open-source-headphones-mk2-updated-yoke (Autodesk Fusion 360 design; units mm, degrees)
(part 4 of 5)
sketch "50mm PM Label" plane through (0, 0, 0) normal (0, 0, -1) x axis (1, 0, 0)
  line L1 (1, -18.9737) -> (1, -23.9792)
  line L2 (14.6475, -19.0119) -> (11.43, -15.1775)
  line L3 (9.9868, 4.6112) -> (6.5, 2.5981)
  line L4 (1, -6.9282) -> (1, -10.9545)
  line L5 (1, 16.9706) -> (1, 12.9615)
  line L6 (10.725, 7.3468) -> (14.1969, 9.3513)
  line L7 (-8.9868, 6.3433) -> (-5.5, 4.3301)
  line L8 (5.5, 4.3301) -> (8.9868, 6.3433)
  line L9 (-1, -16.9706) -> (-1, -12.9615)
  line L10 (-10.725, -7.3468) -> (-14.1969, -9.3513)
  line L11 (-11.725, 5.6147) -> (-15.1969, 7.6193)
  line L12 (-15.1969, -7.6193) -> (-11.725, -5.6147)
  line L13 (11.725, -5.6147) -> (15.1969, -7.6193)
  line L14 (15.1969, 7.6193) -> (11.725, 5.6147)
  line L15 (1, -12.9615) -> (1, -16.9706)
  line L16 (14.1969, -9.3513) -> (10.725, -7.3468)
  line L17 (-1, 12.9615) -> (-1, 16.9706)
  line L18 (-14.1969, 9.3513) -> (-10.725, 7.3468)
  line L19 (-1, -10.9545) -> (-1, -6.9282)
  line L20 (-6.5, 2.5981) -> (-9.9868, 4.6112)
  line L21 (-11.43, -15.1775) -> (-14.6475, -19.0119)
  line L22 (-1, -23.9792) -> (-1, -18.9737)
  line L23 (-18.5118, -4.2796) -> (-23.4412, -5.1487)
  line L24 (-16.1795, -17.7263) -> (-12.9621, -13.8919)
  line L25 (-16.9317, 8.6208) -> (-21.2666, 11.1236)
  line L26 (-23.7885, -3.1791) -> (-18.8591, -2.3099)
  line L27 (-7.4291, 17.4874) -> (-9.141, 22.191)
  line L28 (-20.2666, 12.8556) -> (-15.9317, 10.3529)
  line L29 (5.5497, 18.1714) -> (7.2617, 22.8751)
  line L30 (-7.2617, 22.8751) -> (-5.5497, 18.1714)
  line L31 (15.9317, 10.3529) -> (20.2666, 12.8556)
  line L32 (9.141, 22.191) -> (7.4291, 17.4874)
  line L33 (18.8591, -2.3099) -> (23.7885, -3.1791)
  line L34 (21.2666, 11.1236) -> (16.9317, 8.6208)
  line L35 (12.9621, -13.8919) -> (16.1795, -17.7263)
  line L36 (23.4412, -5.1487) -> (18.5118, -4.2796)
  line L37 (27.3973, 19.1838) -> (24.0432, 16.8352)
  line L38 (24.0432, -16.8352) -> (27.3973, -19.1838)
  line L39 (-17.7523, 28.4096) -> (-15.6326, 25.0174)
  line L40 (15.6326, 25.0174) -> (17.7523, 28.4096)
  line L41 (-27.3973, -19.1838) -> (-24.0432, -16.8352)
  line L42 (-24.0432, 16.8352) -> (-27.3973, 19.1838)
  line L43 (17.7523, -28.4096) -> (15.6326, -25.0174)
  line L44 (-15.6326, -25.0174) -> (-17.7523, -28.4096)
  curve K1 (0, 52) -> (0, 52)
  curve K2
  curve K3
  curve K4
  curve K5
  arc A1 centre (0, 0) radius 19 clockwise from (11.43, -15.1775) to (1, -18.9737)
  arc A2 centre (0, 0) radius 24 clockwise from (14.6475, -19.0119) to (1, -23.9792)
  arc A3 centre (0, 0) radius 11 clockwise from (9.9868, 4.6112) to (1, -10.9545)
  arc A4 centre (0, 0) radius 7 clockwise from (6.5, 2.5981) to (1, -6.9282)
  arc A5 centre (0, 0) radius 17 clockwise from (1, 16.9706) to (14.1969, 9.3513)
  arc A6 centre (0, 0) radius 13 clockwise from (1, 12.9615) to (10.725, 7.3468)
  circle C1 centre (0, 0) radius 5
  arc A7 centre (0, 0) radius 11 clockwise from (-8.9868, 6.3433) to (8.9868, 6.3433)
  arc A8 centre (0, 0) radius 7 clockwise from (-5.5, 4.3301) to (5.5, 4.3301)
  arc A9 centre (0, 0) radius 17 clockwise from (-1, -16.9706) to (-14.1969, -9.3513)
  arc A10 centre (0, 0) radius 13 clockwise from (-1, -12.9615) to (-10.725, -7.3468)
  arc A11 centre (0, 0) radius 17 clockwise from (-15.1969, -7.6193) to (-15.1969, 7.6193)
  arc A12 centre (0, 0) radius 13 clockwise from (-11.725, -5.6147) to (-11.725, 5.6147)
  arc A13 centre (0, 0) radius 17 clockwise from (15.1969, 7.6193) to (15.1969, -7.6193)
  arc A14 centre (0, 0) radius 13 clockwise from (11.725, 5.6147) to (11.725, -5.6147)
  arc A15 centre (0, 0) radius 17 clockwise from (14.1969, -9.3513) to (1, -16.9706)
  arc A16 centre (0, 0) radius 13 clockwise from (10.725, -7.3468) to (1, -12.9615)
  arc A17 centre (0, 0) radius 17 clockwise from (-14.1969, 9.3513) to (-1, 16.9706)
  arc A18 centre (0, 0) radius 13 clockwise from (-10.725, 7.3468) to (-1, 12.9615)
  arc A19 centre (0, 0) radius 11 clockwise from (-1, -10.9545) to (-9.9868, 4.6112)
  arc A20 centre (0, 0) radius 7 clockwise from (-1, -6.9282) to (-6.5, 2.5981)
  arc A21 centre (0, 0) radius 19 clockwise from (-1, -18.9737) to (-11.43, -15.1775)
  arc A22 centre (0, 0) radius 24 clockwise from (-1, -23.9792) to (-14.6475, -19.0119)
  arc A23 centre (0, 0) radius 19 clockwise from (-12.9621, -13.8919) to (-18.5118, -4.2796)
  arc A24 centre (0, 0) radius 24 clockwise from (-16.1795, -17.7263) to (-23.4412, -5.1487)
  arc A25 centre (0, 0) radius 19 clockwise from (-18.8591, -2.3099) to (-16.9317, 8.6208)
  arc A26 centre (0, 0) radius 24 clockwise from (-23.7885, -3.1791) to (-21.2666, 11.1236)
  arc A27 centre (0, 0) radius 19 clockwise from (-15.9317, 10.3529) to (-7.4291, 17.4874)
  arc A28 centre (0, 0) radius 24 clockwise from (-20.2666, 12.8556) to (-9.141, 22.191)
  arc A29 centre (0, 0) radius 19 clockwise from (-5.5497, 18.1714) to (5.5497, 18.1714)
  arc A30 centre (0, 0) radius 24 clockwise from (-7.2617, 22.8751) to (7.2617, 22.8751)
  arc A31 centre (0, 0) radius 19 clockwise from (7.4291, 17.4874) to (15.9317, 10.3529)
  arc A32 centre (0, 0) radius 24 clockwise from (9.141, 22.191) to (20.2666, 12.8556)
  arc A33 centre (0, 0) radius 19 clockwise from (16.9317, 8.6208) to (18.8591, -2.3099)
  arc A34 centre (0, 0) radius 24 clockwise from (21.2666, 11.1236) to (23.7885, -3.1791)
  arc A35 centre (0, 0) radius 24 clockwise from (23.4412, -5.1487) to (16.1795, -17.7263)
  arc A36 centre (0, 0) radius 19 clockwise from (18.5118, -4.2796) to (12.9621, -13.8919)
  closed curve K6 centre (0, 0)
  closed curve K7 centre (0, 0)
  arc A37 centre (0, 0) radius 33.5 clockwise from (-17.7523, 28.4096) to (17.7523, 28.4096)
  arc A38 centre (0, 0) radius 29.5 clockwise from (-15.6326, 25.0174) to (15.6326, 25.0174)
  closed curve K8 centre (0, 0)
  closed curve K9 centre (0, 0)
  arc A39 centre (0, 0) radius 33.5 clockwise from (17.7523, -28.4096) to (-17.7523, -28.4096)
  arc A40 centre (0, 0) radius 29.5 clockwise from (15.6326, -25.0174) to (-15.6326, -25.0174)
  circle C2 centre (-22.8469, 24.5003) radius 4
  circle C3 centre (22.8469, 24.5003) radius 4
  circle C4 centre (-22.8469, -24.5003) radius 4
  circle C5 centre (22.8469, -24.5003) radius 4
  coincident K1
  dimension "d517" Text1-Height = 10
extrude "Extrude28" cut sketch "50mm PM Label" against normal blind 0.5
sketch "50mm DC Label" plane through (0, 0, 20) normal (0, 0, -1) x axis (1, 0, 0)
  line L1 (8, 23.8964) -> (8, 32.5308)
  line L2 (-8, 32.5308) -> (-8, 23.8964)
  line L3 (27.3973, 19.1838) -> (24.0432, 16.8352)
  line L4 (24.0432, -16.8352) -> (27.3973, -19.1838)
  line L5 (17.7523, -28.4096) -> (15.6326, -25.0174)
  line L6 (-15.6326, -25.0174) -> (-17.7523, -28.4096)
  line L7 (-27.3973, -19.1838) -> (-24.0432, -16.8352)
  line L8 (-24.0432, 16.8352) -> (-27.3973, 19.1838)
  line L9 (6, 55.0308) -> (8, 54.1239)
  line L10 (-6, 55.0308) -> (6, 55.0308)
  line L11 (-8, 54.1239) -> (-6, 55.0308)
  curve K1
  curve K2
  curve K3
  curve K4
  line L12 (45, -1.2179) -> (45, -5.5)
  line L13 (48, -1.2179) -> (45, -1.2179)
  line L14 (48, 3.5) -> (48, -1.2179)
  line L15 (45, 3.5) -> (48, 3.5)
  line L16 (45, 5.5) -> (45, 3.5)
  line L17 (44.7744, 5.5) -> (45, 5.5)
  line L18 (-45, 5.5) -> (-44.7744, 5.5)
  line L19 (-45, 3.5) -> (-45, 5.5)
  line L20 (-48, 3.5) -> (-45, 3.5)
  line L21 (-48, -1.2179) -> (-48, 3.5)
  line L22 (-45, -1.2179) -> (-48, -1.2179)
  line L23 (-45, -5.5) -> (-45, -1.2179)
  line L24 (-44.7744, -5.5) -> (-45, -5.5)
  line L25 (45, -5.5) -> (44.7744, -5.5)
  arc A1 centre (0, 0) radius 25.2 clockwise from (8, 23.8964) to (-8, 23.8964)
  arc A2 centre (0, 0) radius 33.5 clockwise from (-8, 32.5308) to (8, 32.5308)
  closed curve K5 centre (0, 0)
  closed curve K6 centre (0, 0)
  arc A3 centre (0, 0) radius 27.5 clockwise from (26.4189, 7.6348) to (26.4189, -7.6348)
  closed curve K7 centre (0, 0)
  circle C1 centre (22.8469, -24.5003) radius 2.2
  circle C2 centre (22.8469, 24.5003) radius 2.2
  circle C3 centre (-22.8469, -24.5003) radius 2.2
  circle C4 centre (-22.8469, 24.5003) radius 2.2
  arc A4 centre (0, 0) radius 33.5 clockwise from (17.7523, -28.4096) to (-17.7523, -28.4096)
  arc A5 centre (0, 0) radius 29.5 clockwise from (15.6326, -25.0174) to (-15.6326, -25.0174)
  closed curve K8 centre (0, 0)
  closed curve K9 centre (0, 0)
  closed curve K10 centre (0, 0)
  closed curve K11 centre (0, 0)
  arc A6 centre (0, 0) radius 27.5 clockwise from (-26.4189, -7.6348) to (-26.4189, 7.6348)
  closed curve K12 centre (0, 0)
  closed curve K13 centre (0, 0)
  dimension "d520" Text1-Height = 10
extrude "Extrude29" cut sketch "50mm DC Label" against normal blind 0.5
sketch "52mm PM Label" plane through (0, 0, 0) normal (0, 0, -1) x axis (1, 0, 0)
  line L1 (101, -19.975) -> (101, -24.98)
  line L2 (115.2908, -19.7786) -> (112.0736, -15.9445)
  line L3 (109.9868, 4.6112) -> (106.5, 2.5981)
  line L4 (101, -6.9282) -> (101, -10.9545)
  line L5 (101, 17.9722) -> (101, 12.9615)
  line L6 (110.725, 7.3468) -> (115.0644, 9.8521)
  line L7 (91.0132, 6.3433) -> (94.5, 4.3301)
  line L8 (105.5, 4.3301) -> (108.9868, 6.3433)
  line L9 (99, -17.9722) -> (99, -12.9615)
  line L10 (89.275, -7.3468) -> (84.9356, -9.8521)
  line L11 (88.275, 5.6147) -> (83.9356, 8.1201)
  line L12 (83.9356, -8.1201) -> (88.275, -5.6147)
  line L13 (111.725, -5.6147) -> (116.0644, -8.1201)
  line L14 (116.0644, 8.1201) -> (111.725, 5.6147)
  line L15 (101, -12.9615) -> (101, -17.9722)
  line L16 (115.0644, -9.8521) -> (110.725, -7.3468)
  line L17 (99, 12.9615) -> (99, 17.9722)
  line L18 (84.9356, 9.8521) -> (89.275, 7.3468)
  line L19 (99, -10.9545) -> (99, -6.9282)
  line L20 (93.5, 2.5981) -> (90.0132, 4.6112)
  line L21 (87.9264, -15.9445) -> (84.7092, -19.7786)
  line L22 (99, -24.98) -> (99, -19.975)
  line L23 (80.5021, -4.4534) -> (75.5732, -5.3225)
  line L24 (83.1771, -18.493) -> (86.3943, -14.6589)
  line L25 (82.2012, 9.1215) -> (77.8667, 11.624)
  line L26 (75.2259, -3.3529) -> (80.1548, -2.4838)
  line L27 (92.2285, 18.4283) -> (90.5166, 23.1315)
  line L28 (78.8667, 13.356) -> (83.2012, 10.8535)
  line L29 (105.8922, 19.1124) -> (107.604, 23.8155)
  line L30 (92.396, 23.8155) -> (94.1078, 19.1124)
  line L31 (116.7988, 10.8535) -> (121.1333, 13.356)
  line L32 (109.4834, 23.1315) -> (107.7715, 18.4283)
  line L33 (119.8452, -2.4838) -> (124.7741, -3.3529)
  line L34 (122.1333, 11.624) -> (117.7988, 9.1215)
  line L35 (113.6057, -14.6589) -> (116.8229, -18.493)
  line L36 (124.4268, -5.3225) -> (119.4979, -4.4534)
  line L37 (127.3973, 19.1838) -> (124.8888, 17.4274)
  line L38 (124.8888, -17.4274) -> (127.3973, -19.1838)
  curve K1 (124.8888, -17.4274) -> (124.8888, 17.4274)
  line L39 (82.2477, 28.4096) -> (84.3674, 25.0174)
  line L40 (115.6326, 25.0174) -> (117.7523, 28.4096)
  line L41 (72.6027, -19.1838) -> (75.1112, -17.4274)
  line L42 (75.1112, 17.4274) -> (72.6027, 19.1838)
  curve K2 (75.1112, 17.4274) -> (75.1112, -17.4274)
  line L43 (117.7523, -28.4096) -> (115.6326, -25.0174)
  line L44 (84.3674, -25.0174) -> (82.2477, -28.4096)
  curve K3 (100, 52) -> (100, 52)
  curve K4
  curve K5
  curve K6
  curve K7
  arc A1 centre (100, 0) radius 20 clockwise from (112.0736, -15.9445) to (101, -19.975)
  arc A2 centre (100, 0) radius 25 clockwise from (115.2908, -19.7786) to (101, -24.98)
  arc A3 centre (100, 0) radius 11 clockwise from (109.9868, 4.6112) to (101, -10.9545)
  arc A4 centre (100, 0) radius 7 clockwise from (106.5, 2.5981) to (101, -6.9282)
  arc A5 centre (100, 0) radius 18 clockwise from (101, 17.9722) to (115.0644, 9.8521)
  arc A6 centre (100, 0) radius 13 clockwise from (101, 12.9615) to (110.725, 7.3468)
  circle C1 centre (100, 0) radius 5
  arc A7 centre (100, 0) radius 11 clockwise from (91.0132, 6.3433) to (108.9868, 6.3433)
  arc A8 centre (100, 0) radius 7 clockwise from (94.5, 4.3301) to (105.5, 4.3301)
  arc A9 centre (100, 0) radius 18 clockwise from (99, -17.9722) to (84.9356, -9.8521)
  arc A10 centre (100, 0) radius 13 clockwise from (99, -12.9615) to (89.275, -7.3468)
  arc A11 centre (100, 0) radius 18 clockwise from (83.9356, -8.1201) to (83.9356, 8.1201)
  arc A12 centre (100, 0) radius 13 clockwise from (88.275, -5.6147) to (88.275, 5.6147)
  arc A13 centre (100, 0) radius 18 clockwise from (116.0644, 8.1201) to (116.0644, -8.1201)
  arc A14 centre (100, 0) radius 13 clockwise from (111.725, 5.6147) to (111.725, -5.6147)
  arc A15 centre (100, 0) radius 18 clockwise from (115.0644, -9.8521) to (101, -17.9722)
  arc A16 centre (100, 0) radius 13 clockwise from (110.725, -7.3468) to (101, -12.9615)
  arc A17 centre (100, 0) radius 18 clockwise from (84.9356, 9.8521) to (99, 17.9722)
  arc A18 centre (100, 0) radius 13 clockwise from (89.275, 7.3468) to (99, 12.9615)
  arc A19 centre (100, 0) radius 11 clockwise from (99, -10.9545) to (90.0132, 4.6112)
  arc A20 centre (100, 0) radius 7 clockwise from (99, -6.9282) to (93.5, 2.5981)
  arc A21 centre (100, 0) radius 20 clockwise from (99, -19.975) to (87.9264, -15.9445)
  arc A22 centre (100, 0) radius 25 clockwise from (99, -24.98) to (84.7092, -19.7786)
  arc A23 centre (100, 0) radius 20 clockwise from (86.3943, -14.6589) to (80.5021, -4.4534)
  arc A24 centre (100, 0) radius 25 clockwise from (83.1771, -18.493) to (75.5732, -5.3225)
  arc A25 centre (100, 0) radius 20 clockwise from (80.1548, -2.4838) to (82.2012, 9.1215)
  arc A26 centre (100, 0) radius 25 clockwise from (75.2259, -3.3529) to (77.8667, 11.624)
  arc A27 centre (100, 0) radius 20 clockwise from (83.2012, 10.8535) to (92.2285, 18.4283)
  arc A28 centre (100, 0) radius 25 clockwise from (78.8667, 13.356) to (90.5166, 23.1315)
  arc A29 centre (100, 0) radius 20 clockwise from (94.1078, 19.1124) to (105.8922, 19.1124)
  arc A30 centre (100, 0) radius 25 clockwise from (92.396, 23.8155) to (107.604, 23.8155)
  arc A31 centre (100, 0) radius 20 clockwise from (107.7715, 18.4283) to (116.7988, 10.8535)
  arc A32 centre (100, 0) radius 25 clockwise from (109.4834, 23.1315) to (121.1333, 13.356)
  arc A33 centre (100, 0) radius 20 clockwise from (117.7988, 9.1215) to (119.8452, -2.4838)
  arc A34 centre (100, 0) radius 25 clockwise from (122.1333, 11.624) to (124.7741, -3.3529)
  arc A35 centre (100, 0) radius 25 clockwise from (124.4268, -5.3225) to (116.8229, -18.493)
  arc A36 centre (100, 0) radius 20 clockwise from (119.4979, -4.4534) to (113.6057, -14.6589)
  closed curve K8 centre (100, 0)
  arc A37 centre (100, 0) radius 33.5 clockwise from (82.2477, 28.4096) to (117.7523, 28.4096)
  arc A38 centre (100, 0) radius 29.5 clockwise from (84.3674, 25.0174) to (115.6326, 25.0174)
  closed curve K9 centre (100, 0)
  arc A39 centre (100, 0) radius 33.5 clockwise from (117.7523, -28.4096) to (82.2477, -28.4096)
  arc A40 centre (100, 0) radius 29.5 clockwise from (115.6326, -25.0174) to (84.3674, -25.0174)
  circle C2 centre (77.1531, 24.5003) radius 4
  circle C3 centre (122.8469, 24.5003) radius 4
  circle C4 centre (77.1531, -24.5003) radius 4
  circle C5 centre (122.8469, -24.5003) radius 4
  dimension "d523" Text1-Height = 10
sketch "52mm DC Label" plane through (0, 0, 20) normal (0, 0, -1) x axis (1, 0, 0)
  line L1 (117.7523, -28.4096) -> (115.6326, -25.0174)
  line L2 (84.3674, -25.0174) -> (82.2477, -28.4096)
  curve K1 (124.8888, 17.4274) -> (127.1497, 9.3052)
  line L3 (127.3973, 19.1838) -> (124.8888, 17.4274)
  line L4 (124.8888, -17.4274) -> (127.3973, -19.1838)
  curve K2 (127.1497, -9.3052) -> (124.8888, -17.4274)
  line L5 (108, 24.9487) -> (108, 32.5308)
  line L6 (92, 32.5308) -> (92, 24.9487)
  curve K3 (75.1112, -17.4274) -> (72.8503, -9.3052)
  line L7 (72.6027, -19.1838) -> (75.1112, -17.4274)
  line L8 (75.1112, 17.4274) -> (72.6027, 19.1838)
  curve K4 (72.8503, 9.3052) -> (75.1112, 17.4274)
  line L9 (106, 55.0308) -> (108, 54.1239)
  line L10 (94, 55.0308) -> (106, 55.0308)
  line L11 (92, 54.1239) -> (94, 55.0308)
  curve K5
  curve K6
  curve K7
  curve K8
  line L12 (145, -1.2179) -> (145, -5.5)
  line L13 (148, -1.2179) -> (145, -1.2179)
  line L14 (148, 3.5) -> (148, -1.2179)
  line L15 (145, 3.5) -> (148, 3.5)
  line L16 (145, 5.5) -> (145, 3.5)
  line L17 (144.7744, 5.5) -> (145, 5.5)
  line L18 (55, 5.5) -> (55.2256, 5.5)
  line L19 (55, 3.5) -> (55, 5.5)
  line L20 (52, 3.5) -> (55, 3.5)
  line L21 (52, -1.2179) -> (52, 3.5)
  line L22 (55, -1.2179) -> (52, -1.2179)
  line L23 (55, -5.5) -> (55, -1.2179)
  line L24 (55.2256, -5.5) -> (55, -5.5)
  line L25 (145, -5.5) -> (144.7744, -5.5)
  arc A1 centre (100, 0) radius 33.5 clockwise from (117.7523, -28.4096) to (82.2477, -28.4096)
  arc A2 centre (100, 0) radius 29.5 clockwise from (115.6326, -25.0174) to (84.3674, -25.0174)
  closed curve K9 centre (100, 0)
  arc A3 centre (100, 0) radius 28.7 clockwise from (127.1497, 9.3052) to (127.1497, -9.3052)
  arc A4 centre (100, 0) radius 26.2 clockwise from (108, 24.9487) to (92, 24.9487)
  arc A5 centre (100, 0) radius 33.5 clockwise from (92, 32.5308) to (108, 32.5308)
  closed curve K10 centre (100, 0)
  arc A6 centre (100, 0) radius 28.7 clockwise from (72.8503, -9.3052) to (72.8503, 9.3052)
  circle C1 centre (122.8469, -24.5003) radius 2.2
  circle C2 centre (122.8469, 24.5003) radius 2.2
  circle C3 centre (77.1531, -24.5003) radius 2.2
  circle C4 centre (77.1531, 24.5003) radius 2.2
  closed curve K11 centre (100, 0)
  closed curve K12 centre (100, 0)
  closed curve K13 centre (100, 0)
  dimension "d524" Text1-Height = 10
extrude "Extrude14" cut sketch "52mm PM Label" against normal blind 0.5
extrude "Extrude15" cut sketch "52mm DC Label" against normal blind 0.5
sketch "40mm PM Label" plane through (0, 0, 0) normal (0, 0, -1) x axis (1, 0, 0)
  line L1 (-1, -130.9545) -> (-1, -126.9282)
  line L2 (-6.5, -117.4019) -> (-9.9868, -115.3888)
  line L3 (-1, -107.0385) -> (-1, -103.0294)
  line L4 (-14.1969, -110.6487) -> (-10.725, -112.6532)
  line L5 (1, -132.9615) -> (1, -136.9706)
  line L6 (14.1969, -129.3513) -> (10.725, -127.3468)
  line L7 (11.725, -125.6147) -> (15.1969, -127.6193)
  line L8 (15.1969, -112.3807) -> (11.725, -114.3853)
  line L9 (-11.725, -114.3853) -> (-15.1969, -112.3807)
  line L10 (-15.1969, -127.6193) -> (-11.725, -125.6147)
  line L11 (-1, -136.9706) -> (-1, -132.9615)
  line L12 (-10.725, -127.3468) -> (-14.1969, -129.3513)
  line L13 (-8.9868, -113.6567) -> (-5.5, -115.6699)
  line L14 (5.5, -115.6699) -> (8.9868, -113.6567)
  line L15 (1, -103.0294) -> (1, -107.0385)
  line L16 (10.725, -112.6532) -> (14.1969, -110.6487)
  line L17 (9.9868, -115.3888) -> (6.5, -117.4019)
  line L18 (1, -126.9282) -> (1, -130.9545)
  line L19 (27.3973, -100.8162) -> (24.0432, -103.1648)
  line L20 (24.0432, -136.8352) -> (27.3973, -139.1838)
  line L21 (-17.7523, -91.5904) -> (-15.6326, -94.9826)
  line L22 (15.6326, -94.9826) -> (17.7523, -91.5904)
  line L23 (-27.3973, -139.1838) -> (-24.0432, -136.8352)
  line L24 (-24.0432, -103.1648) -> (-27.3973, -100.8162)
  line L25 (17.7523, -148.4096) -> (15.6326, -145.0174)
  line L26 (-15.6326, -145.0174) -> (-17.7523, -148.4096)
  curve K1 (0, -68) -> (0, -68)
  curve K2
  curve K3
  curve K4
  curve K5
  arc A1 centre (0, -120) radius 11 clockwise from (-1, -130.9545) to (-9.9868, -115.3888)
  arc A2 centre (0, -120) radius 7 clockwise from (-1, -126.9282) to (-6.5, -117.4019)
  arc A3 centre (0, -120) radius 17 clockwise from (-14.1969, -110.6487) to (-1, -103.0294)
  arc A4 centre (0, -120) radius 13 clockwise from (-10.725, -112.6532) to (-1, -107.0385)
  arc A5 centre (0, -120) radius 17 clockwise from (14.1969, -129.3513) to (1, -136.9706)
  arc A6 centre (0, -120) radius 13 clockwise from (10.725, -127.3468) to (1, -132.9615)
  arc A7 centre (0, -120) radius 17 clockwise from (15.1969, -112.3807) to (15.1969, -127.6193)
  arc A8 centre (0, -120) radius 13 clockwise from (11.725, -114.3853) to (11.725, -125.6147)
  arc A9 centre (0, -120) radius 17 clockwise from (-15.1969, -127.6193) to (-15.1969, -112.3807)
  arc A10 centre (0, -120) radius 13 clockwise from (-11.725, -125.6147) to (-11.725, -114.3853)
  arc A11 centre (0, -120) radius 17 clockwise from (-1, -136.9706) to (-14.1969, -129.3513)
  arc A12 centre (0, -120) radius 13 clockwise from (-1, -132.9615) to (-10.725, -127.3468)
  arc A13 centre (0, -120) radius 11 clockwise from (-8.9868, -113.6567) to (8.9868, -113.6567)
  arc A14 centre (0, -120) radius 7 clockwise from (-5.5, -115.6699) to (5.5, -115.6699)
  circle C1 centre (0, -120) radius 5
  arc A15 centre (0, -120) radius 17 clockwise from (1, -103.0294) to (14.1969, -110.6487)
  arc A16 centre (0, -120) radius 13 clockwise from (1, -107.0385) to (10.725, -112.6532)
  arc A17 centre (0, -120) radius 11 clockwise from (9.9868, -115.3888) to (1, -130.9545)
  arc A18 centre (0, -120) radius 7 clockwise from (6.5, -117.4019) to (1, -126.9282)
  closed curve K6 centre (0, -120)
  closed curve K7 centre (0, -120)
  arc A19 centre (0, -120) radius 33.5 clockwise from (-17.7523, -91.5904) to (17.7523, -91.5904)
  arc A20 centre (0, -120) radius 29.5 clockwise from (-15.6326, -94.9826) to (15.6326, -94.9826)
  closed curve K8 centre (0, -120)
  closed curve K9 centre (0, -120)
  arc A21 centre (0, -120) radius 33.5 clockwise from (17.7523, -148.4096) to (-17.7523, -148.4096)
  arc A22 centre (0, -120) radius 29.5 clockwise from (15.6326, -145.0174) to (-15.6326, -145.0174)
  circle C2 centre (-22.8469, -95.4997) radius 4
  circle C3 centre (22.8469, -95.4997) radius 4
  circle C4 centre (-22.8469, -144.5003) radius 4
  circle C5 centre (22.8469, -144.5003) radius 4
  dimension "d529" Text1-Height = 10
sketch "40mm DC Label" plane through (0, 0, 20) normal (0, 0, -1) x axis (1, 0, 0)
  line L1 (8, -101.1254) -> (8, -92.6458)
  line L2 (-8, -92.6458) -> (-8, -101.1254)
  line L3 (27.3973, -100.8162) -> (24.0432, -103.1648)
  line L4 (24.0432, -136.8352) -> (27.3973, -139.1838)
  line L5 (17.7523, -148.4096) -> (15.6326, -145.0174)
  line L6 (-15.6326, -145.0174) -> (-17.7523, -148.4096)
  line L7 (-27.3973, -139.1838) -> (-24.0432, -136.8352)
  line L8 (-24.0432, -103.1648) -> (-27.3973, -100.8162)
  line L9 (6, -64.9692) -> (8, -65.8761)
  line L10 (-6, -64.9692) -> (6, -64.9692)
  line L11 (-8, -65.8761) -> (-6, -64.9692)
  curve K1
  curve K2
  curve K3
  curve K4
  line L12 (45, -121.2179) -> (45, -125.5)
  line L13 (48, -121.2179) -> (45, -121.2179)
  line L14 (48, -116.5) -> (48, -121.2179)
  line L15 (45, -116.5) -> (48, -116.5)
  line L16 (45, -114.5) -> (45, -116.5)
  line L17 (44.7744, -114.5) -> (45, -114.5)
  line L18 (-45, -114.5) -> (-44.7744, -114.5)
  line L19 (-45, -116.5) -> (-45, -114.5)
  line L20 (-48, -116.5) -> (-45, -116.5)
  line L21 (-48, -121.2179) -> (-48, -116.5)
  line L22 (-45, -121.2179) -> (-48, -121.2179)
  line L23 (-45, -125.5) -> (-45, -121.2179)
  line L24 (-44.7744, -125.5) -> (-45, -125.5)
  line L25 (45, -125.5) -> (44.7744, -125.5)
  arc A1 centre (0, -120) radius 20.5 clockwise from (8, -101.1254) to (-8, -101.1254)
  arc A2 centre (0, -120) radius 28.5 clockwise from (-8, -92.6458) to (8, -92.6458)
  closed curve K5 centre (0, -120)
  closed curve K6 centre (0, -120)
  arc A3 centre (0, -120) radius 27.5 clockwise from (26.4189, -112.3652) to (26.4189, -127.6348)
  closed curve K7 centre (0, -120)
  circle C1 centre (22.8469, -144.5003) radius 2.2
  circle C2 centre (22.8469, -95.4997) radius 2.2
  circle C3 centre (-22.8469, -144.5003) radius 2.2
  circle C4 centre (-22.8469, -95.4997) radius 2.2
  arc A4 centre (0, -120) radius 33.5 clockwise from (17.7523, -148.4096) to (-17.7523, -148.4096)
  arc A5 centre (0, -120) radius 29.5 clockwise from (15.6326, -145.0174) to (-15.6326, -145.0174)
  closed curve K8 centre (0, -120)
  arc A6 centre (0, -120) radius 27.5 clockwise from (-26.4189, -127.6348) to (-26.4189, -112.3652)
  closed curve K9 centre (0, -120)
  closed curve K10 centre (0, -120)
  closed curve K11 centre (0, -120)
  closed curve K12 centre (0, -120)
  closed curve K13 centre (0, -120)
  dimension "d530" Text1-Height = 10
extrude "Extrude16" cut sketch "40mm DC Label" against normal blind 0.5
extrude "Extrude17" cut sketch "40mm PM Label" against normal blind 0.5
sketch "44mm PM Label" plane through (0, 0, 0) normal (0, 0, -1) x axis (1, 0, 0)
  line L1 (101, -138.9737) -> (101, -140.9762)
  line L2 (112.7172, -136.7115) -> (111.43, -135.1775)
  line L3 (109.9868, -115.3888) -> (106.5, -117.4019)
  line L4 (101, -126.9282) -> (101, -130.9545)
  line L5 (101, -103.0294) -> (101, -107.0385)
  line L6 (110.725, -112.6532) -> (114.1969, -110.6487)
  line L7 (91.0132, -113.6567) -> (94.5, -115.6699)
  line L8 (105.5, -115.6699) -> (108.9868, -113.6567)
  line L9 (99, -136.9706) -> (99, -132.9615)
  line L10 (89.275, -127.3468) -> (85.8031, -129.3513)
  line L11 (88.275, -114.3853) -> (84.8031, -112.3807)
  line L12 (84.8031, -127.6193) -> (88.275, -125.6147)
  line L13 (111.725, -125.6147) -> (115.1969, -127.6193)
  line L14 (115.1969, -112.3807) -> (111.725, -114.3853)
  line L15 (101, -132.9615) -> (101, -136.9706)
  line L16 (114.1969, -129.3513) -> (110.725, -127.3468)
  line L17 (99, -107.0385) -> (99, -103.0294)
  line L18 (85.8031, -110.6487) -> (89.275, -112.6532)
  line L19 (99, -130.9545) -> (99, -126.9282)
  line L20 (93.5, -117.4019) -> (90.0132, -115.3888)
  line L21 (88.57, -135.1775) -> (87.2828, -136.7115)
  line L22 (99, -140.9762) -> (99, -138.9737)
  line L23 (81.4882, -124.2796) -> (79.5161, -124.6273)
  line L24 (85.7507, -135.4259) -> (87.0379, -133.8919)
  line L25 (83.0683, -111.3792) -> (81.3341, -110.3779)
  line L26 (79.1689, -122.6577) -> (81.1409, -122.3099)
  line L27 (92.5709, -102.5126) -> (91.886, -100.6309)
  line L28 (82.3341, -108.6459) -> (84.0683, -109.6471)
  line L29 (105.5497, -101.8286) -> (106.2346, -99.9468)
  line L30 (93.7654, -99.9468) -> (94.4503, -101.8286)
  line L31 (115.9317, -109.6471) -> (117.6659, -108.6459)
  line L32 (108.114, -100.6309) -> (107.4291, -102.5126)
  line L33 (118.8591, -122.3099) -> (120.8311, -122.6577)
  line L34 (118.6659, -110.3779) -> (116.9317, -111.3792)
  line L35 (112.9621, -133.8919) -> (114.2493, -135.4259)
  line L36 (120.4839, -124.6273) -> (118.5118, -124.2796)
  line L37 (127.3973, -100.8162) -> (124.0432, -103.1648)
  line L38 (124.0432, -136.8352) -> (127.3973, -139.1838)
  line L39 (82.2477, -91.5904) -> (84.3674, -94.9826)
  line L40 (115.6326, -94.9826) -> (117.7523, -91.5904)
  line L41 (72.6027, -139.1838) -> (75.9568, -136.8352)
  line L42 (75.9568, -103.1648) -> (72.6027, -100.8162)
  line L43 (117.7523, -148.4096) -> (115.6326, -145.0174)
  line L44 (84.3674, -145.0174) -> (82.2477, -148.4096)
  curve K1 (100, -68) -> (100, -68)
  curve K2
  curve K3
  curve K4
  curve K5
  arc A1 centre (100, -120) radius 19 clockwise from (111.43, -135.1775) to (101, -138.9737)
  arc A2 centre (100, -120) radius 21 clockwise from (112.7172, -136.7115) to (101, -140.9762)
  arc A3 centre (100, -120) radius 11 clockwise from (109.9868, -115.3888) to (101, -130.9545)
  arc A4 centre (100, -120) radius 7 clockwise from (106.5, -117.4019) to (101, -126.9282)
  arc A5 centre (100, -120) radius 17 clockwise from (101, -103.0294) to (114.1969, -110.6487)
  arc A6 centre (100, -120) radius 13 clockwise from (101, -107.0385) to (110.725, -112.6532)
  circle C1 centre (100, -120) radius 5
  arc A7 centre (100, -120) radius 11 clockwise from (91.0132, -113.6567) to (108.9868, -113.6567)
  arc A8 centre (100, -120) radius 7 clockwise from (94.5, -115.6699) to (105.5, -115.6699)
  arc A9 centre (100, -120) radius 17 clockwise from (99, -136.9706) to (85.8031, -129.3513)
  arc A10 centre (100, -120) radius 13 clockwise from (99, -132.9615) to (89.275, -127.3468)
  arc A11 centre (100, -120) radius 17 clockwise from (84.8031, -127.6193) to (84.8031, -112.3807)
  arc A12 centre (100, -120) radius 13 clockwise from (88.275, -125.6147) to (88.275, -114.3853)
  arc A13 centre (100, -120) radius 17 clockwise from (115.1969, -112.3807) to (115.1969, -127.6193)
  arc A14 centre (100, -120) radius 13 clockwise from (111.725, -114.3853) to (111.725, -125.6147)
  arc A15 centre (100, -120) radius 17 clockwise from (114.1969, -129.3513) to (101, -136.9706)
  arc A16 centre (100, -120) radius 13 clockwise from (110.725, -127.3468) to (101, -132.9615)
  arc A17 centre (100, -120) radius 17 clockwise from (85.8031, -110.6487) to (99, -103.0294)
  arc A18 centre (100, -120) radius 13 clockwise from (89.275, -112.6532) to (99, -107.0385)
  arc A19 centre (100, -120) radius 11 clockwise from (99, -130.9545) to (90.0132, -115.3888)
  arc A20 centre (100, -120) radius 7 clockwise from (99, -126.9282) to (93.5, -117.4019)
  arc A21 centre (100, -120) radius 19 clockwise from (99, -138.9737) to (88.57, -135.1775)
  arc A22 centre (100, -120) radius 21 clockwise from (99, -140.9762) to (87.2828, -136.7115)
  arc A23 centre (100, -120) radius 19 clockwise from (87.0379, -133.8919) to (81.4882, -124.2796)
  arc A24 centre (100, -120) radius 21 clockwise from (85.7507, -135.4259) to (79.5161, -124.6273)
  arc A25 centre (100, -120) radius 19 clockwise from (81.1409, -122.3099) to (83.0683, -111.3792)
  arc A26 centre (100, -120) radius 21 clockwise from (79.1689, -122.6577) to (81.3341, -110.3779)
  arc A27 centre (100, -120) radius 19 clockwise from (84.0683, -109.6471) to (92.5709, -102.5126)
  arc A28 centre (100, -120) radius 21 clockwise from (82.3341, -108.6459) to (91.886, -100.6309)
  arc A29 centre (100, -120) radius 19 clockwise from (94.4503, -101.8286) to (105.5497, -101.8286)
  arc A30 centre (100, -120) radius 21 clockwise from (93.7654, -99.9468) to (106.2346, -99.9468)
  arc A31 centre (100, -120) radius 19 clockwise from (107.4291, -102.5126) to (115.9317, -109.6471)
  arc A32 centre (100, -120) radius 21 clockwise from (108.114, -100.6309) to (117.6659, -108.6459)
  arc A33 centre (100, -120) radius 19 clockwise from (116.9317, -111.3792) to (118.8591, -122.3099)
  arc A34 centre (100, -120) radius 21 clockwise from (118.6659, -110.3779) to (120.8311, -122.6577)
  arc A35 centre (100, -120) radius 21 clockwise from (120.4839, -124.6273) to (114.2493, -135.4259)
  arc A36 centre (100, -120) radius 19 clockwise from (118.5118, -124.2796) to (112.9621, -133.8919)
  closed curve K6 centre (100, -120)
  closed curve K7 centre (100, -120)
  arc A37 centre (100, -120) radius 33.5 clockwise from (82.2477, -91.5904) to (117.7523, -91.5904)
  arc A38 centre (100, -120) radius 29.5 clockwise from (84.3674, -94.9826) to (115.6326, -94.9826)
  closed curve K8 centre (100, -120)
  closed curve K9 centre (100, -120)
  arc A39 centre (100, -120) radius 33.5 clockwise from (117.7523, -148.4096) to (82.2477, -148.4096)
  arc A40 centre (100, -120) radius 29.5 clockwise from (115.6326, -145.0174) to (84.3674, -145.0174)
  circle C2 centre (77.1531, -95.4997) radius 4
  circle C3 centre (122.8469, -95.4997) radius 4
  circle C4 centre (77.1531, -144.5003) radius 4
  circle C5 centre (122.8469, -144.5003) radius 4
  dimension "d535" Text1-Height = 10
sketch "44mm DC Label" plane through (0, 0, 20) normal (0, 0, -1) x axis (1, 0, 0)
  line L1 (108, -99.2915) -> (108, -87.4692)
  line L2 (92, -87.4692) -> (92, -99.2915)
  line L3 (127.3973, -100.8162) -> (124.0432, -103.1648)
  line L4 (124.0432, -136.8352) -> (127.3973, -139.1838)
  line L5 (117.7523, -148.4096) -> (115.6326, -145.0174)
  line L6 (84.3674, -145.0174) -> (82.2477, -148.4096)
  line L7 (72.6027, -139.1838) -> (75.9568, -136.8352)
  line L8 (75.9568, -103.1648) -> (72.6027, -100.8162)
  line L9 (106, -64.9692) -> (108, -65.8761)
  line L10 (94, -64.9692) -> (106, -64.9692)
  line L11 (92, -65.8761) -> (94, -64.9692)
  curve K1
  curve K2
  curve K3
  curve K4
  line L12 (145, -121.2179) -> (145, -125.5)
  line L13 (148, -121.2179) -> (145, -121.2179)
  line L14 (148, -116.5) -> (148, -121.2179)
  line L15 (145, -116.5) -> (148, -116.5)
  line L16 (145, -114.5) -> (145, -116.5)
  line L17 (144.7744, -114.5) -> (145, -114.5)
  line L18 (55, -114.5) -> (55.2256, -114.5)
  line L19 (55, -116.5) -> (55, -114.5)
  line L20 (52, -116.5) -> (55, -116.5)
  line L21 (52, -121.2179) -> (52, -116.5)
  line L22 (55, -121.2179) -> (52, -121.2179)
  line L23 (55, -125.5) -> (55, -121.2179)
  line L24 (55.2256, -125.5) -> (55, -125.5)
  line L25 (145, -125.5) -> (144.7744, -125.5)
  arc A1 centre (100, -120) radius 22.2 clockwise from (108, -99.2915) to (92, -99.2915)
  arc A2 centre (100, -120) radius 33.5 clockwise from (92, -87.4692) to (108, -87.4692)
  closed curve K5 centre (100, -120)
  closed curve K6 centre (100, -120)
  arc A3 centre (100, -120) radius 27.5 clockwise from (126.4189, -112.3652) to (126.4189, -127.6348)
  closed curve K7 centre (100, -120)
  circle C1 centre (122.8469, -144.5003) radius 2.2
  circle C2 centre (122.8469, -95.4997) radius 2.2
  circle C3 centre (77.1531, -144.5003) radius 2.2
  circle C4 centre (77.1531, -95.4997) radius 2.2
  arc A4 centre (100, -120) radius 33.5 clockwise from (117.7523, -148.4096) to (82.2477, -148.4096)
  arc A5 centre (100, -120) radius 29.5 clockwise from (115.6326, -145.0174) to (84.3674, -145.0174)
  closed curve K8 centre (100, -120)
  closed curve K9 centre (100, -120)
  closed curve K10 centre (100, -120)
  closed curve K11 centre (100, -120)
  arc A6 centre (100, -120) radius 27.5 clockwise from (73.5811, -127.6348) to (73.5811, -112.3652)
  closed curve K12 centre (100, -120)
  closed curve K13 centre (100, -120)
  dimension "d536" Text1-Height = 10
extrude "Extrude18" cut sketch "44mm PM Label" against normal blind 0.5
extrude "Extrude19" cut sketch "44mm DC Label" against normal blind 0.5
sketch "45mm PM Label" plane through (0, 0, 0) normal (0, 0, -1) x axis (1, 0, 0)
  line L1 (201, -138.9737) -> (201, -141.4767)
  line L2 (213.0389, -137.0949) -> (211.43, -135.1775)
  line L3 (209.9868, -115.3888) -> (206.5, -117.4019)
  line L4 (201, -126.9282) -> (201, -130.9545)
  line L5 (201, -103.0294) -> (201, -107.0385)
  line L6 (210.725, -112.6532) -> (214.1969, -110.6487)
  line L7 (191.0132, -113.6567) -> (194.5, -115.6699)
  line L8 (205.5, -115.6699) -> (208.9868, -113.6567)
  line L9 (199, -136.9706) -> (199, -132.9615)
  line L10 (189.275, -127.3468) -> (185.8031, -129.3513)
  line L11 (188.275, -114.3853) -> (184.8031, -112.3807)
  line L12 (184.8031, -127.6193) -> (188.275, -125.6147)
  line L13 (211.725, -125.6147) -> (215.1969, -127.6193)
  line L14 (215.1969, -112.3807) -> (211.725, -114.3853)
  line L15 (201, -132.9615) -> (201, -136.9706)
  line L16 (214.1969, -129.3513) -> (210.725, -127.3468)
  line L17 (199, -107.0385) -> (199, -103.0294)
  line L18 (185.8031, -110.6487) -> (189.275, -112.6532)
  line L19 (199, -130.9545) -> (199, -126.9282)
  line L20 (193.5, -117.4019) -> (190.0132, -115.3888)
  line L21 (188.57, -135.1775) -> (186.9611, -137.0949)
  line L22 (199, -141.4767) -> (199, -138.9737)
  line L23 (181.4882, -124.2796) -> (179.0232, -124.7142)
  line L24 (185.429, -135.8093) -> (187.0379, -133.8919)
  line L25 (183.0683, -111.3792) -> (180.9006, -110.1277)
  line L26 (178.6759, -122.7446) -> (181.1409, -122.3099)
  line L27 (192.5709, -102.5126) -> (191.7148, -100.1605)
  line L28 (181.9006, -108.3956) -> (184.0683, -109.6471)
  line L29 (205.5497, -101.8286) -> (206.4058, -99.4765)
  line L30 (193.5942, -99.4765) -> (194.4503, -101.8286)
  line L31 (215.9317, -109.6471) -> (218.0994, -108.3956)
  line L32 (208.2852, -100.1605) -> (207.4291, -102.5126)
  line L33 (218.8591, -122.3099) -> (221.3241, -122.7446)
  line L34 (219.0994, -110.1277) -> (216.9317, -111.3792)
  line L35 (212.9621, -133.8919) -> (214.571, -135.8093)
  line L36 (220.9768, -124.7142) -> (218.5118, -124.2796)
  line L37 (227.3973, -100.8162) -> (224.0432, -103.1648)
  line L38 (224.0432, -136.8352) -> (227.3973, -139.1838)
  line L39 (182.2477, -91.5904) -> (184.3674, -94.9826)
  line L40 (215.6326, -94.9826) -> (217.7523, -91.5904)
  line L41 (172.6027, -139.1838) -> (175.9568, -136.8352)
  line L42 (175.9568, -103.1648) -> (172.6027, -100.8162)
  line L43 (217.7523, -148.4096) -> (215.6326, -145.0174)
  line L44 (184.3674, -145.0174) -> (182.2477, -148.4096)
  curve K1 (200, -68) -> (200, -68)
  curve K2
  curve K3
  curve K4
  curve K5
  arc A1 centre (200, -120) radius 19 clockwise from (211.43, -135.1775) to (201, -138.9737)
  arc A2 centre (200, -120) radius 21.5 clockwise from (213.0389, -137.0949) to (201, -141.4767)
  arc A3 centre (200, -120) radius 11 clockwise from (209.9868, -115.3888) to (201, -130.9545)
  arc A4 centre (200, -120) radius 7 clockwise from (206.5, -117.4019) to (201, -126.9282)
  arc A5 centre (200, -120) radius 17 clockwise from (201, -103.0294) to (214.1969, -110.6487)
  arc A6 centre (200, -120) radius 13 clockwise from (201, -107.0385) to (210.725, -112.6532)
  circle C1 centre (200, -120) radius 5
  arc A7 centre (200, -120) radius 11 clockwise from (191.0132, -113.6567) to (208.9868, -113.6567)
  arc A8 centre (200, -120) radius 7 clockwise from (194.5, -115.6699) to (205.5, -115.6699)
  arc A9 centre (200, -120) radius 17 clockwise from (199, -136.9706) to (185.8031, -129.3513)
  arc A10 centre (200, -120) radius 13 clockwise from (199, -132.9615) to (189.275, -127.3468)
  arc A11 centre (200, -120) radius 17 clockwise from (184.8031, -127.6193) to (184.8031, -112.3807)
  arc A12 centre (200, -120) radius 13 clockwise from (188.275, -125.6147) to (188.275, -114.3853)
  arc A13 centre (200, -120) radius 17 clockwise from (215.1969, -112.3807) to (215.1969, -127.6193)
  arc A14 centre (200, -120) radius 13 clockwise from (211.725, -114.3853) to (211.725, -125.6147)
  arc A15 centre (200, -120) radius 17 clockwise from (214.1969, -129.3513) to (201, -136.9706)
  arc A16 centre (200, -120) radius 13 clockwise from (210.725, -127.3468) to (201, -132.9615)
  arc A17 centre (200, -120) radius 17 clockwise from (185.8031, -110.6487) to (199, -103.0294)
  arc A18 centre (200, -120) radius 13 clockwise from (189.275, -112.6532) to (199, -107.0385)
  arc A19 centre (200, -120) radius 11 clockwise from (199, -130.9545) to (190.0132, -115.3888)
  arc A20 centre (200, -120) radius 7 clockwise from (199, -126.9282) to (193.5, -117.4019)
  arc A21 centre (200, -120) radius 19 clockwise from (199, -138.9737) to (188.57, -135.1775)
  arc A22 centre (200, -120) radius 21.5 clockwise from (199, -141.4767) to (186.9611, -137.0949)
  arc A23 centre (200, -120) radius 19 clockwise from (187.0379, -133.8919) to (181.4882, -124.2796)
  arc A24 centre (200, -120) radius 21.5 clockwise from (185.429, -135.8093) to (179.0232, -124.7142)
  arc A25 centre (200, -120) radius 19 clockwise from (181.1409, -122.3099) to (183.0683, -111.3792)
  arc A26 centre (200, -120) radius 21.5 clockwise from (178.6759, -122.7446) to (180.9006, -110.1277)
  arc A27 centre (200, -120) radius 19 clockwise from (184.0683, -109.6471) to (192.5709, -102.5126)
  arc A28 centre (200, -120) radius 21.5 clockwise from (181.9006, -108.3956) to (191.7148, -100.1605)
  arc A29 centre (200, -120) radius 19 clockwise from (194.4503, -101.8286) to (205.5497, -101.8286)
  arc A30 centre (200, -120) radius 21.5 clockwise from (193.5942, -99.4765) to (206.4058, -99.4765)
  arc A31 centre (200, -120) radius 19 clockwise from (207.4291, -102.5126) to (215.9317, -109.6471)
  arc A32 centre (200, -120) radius 21.5 clockwise from (208.2852, -100.1605) to (218.0994, -108.3956)
  arc A33 centre (200, -120) radius 19 clockwise from (216.9317, -111.3792) to (218.8591, -122.3099)
  arc A34 centre (200, -120) radius 21.5 clockwise from (219.0994, -110.1277) to (221.3241, -122.7446)
  arc A35 centre (200, -120) radius 21.5 clockwise from (220.9768, -124.7142) to (214.571, -135.8093)
  arc A36 centre (200, -120) radius 19 clockwise from (218.5118, -124.2796) to (212.9621, -133.8919)
  closed curve K6 centre (200, -120)
  closed curve K7 centre (200, -120)
  arc A37 centre (200, -120) radius 33.5 clockwise from (182.2477, -91.5904) to (217.7523, -91.5904)
  arc A38 centre (200, -120) radius 29.5 clockwise from (184.3674, -94.9826) to (215.6326, -94.9826)
  closed curve K8 centre (200, -120)
  closed curve K9 centre (200, -120)
  arc A39 centre (200, -120) radius 33.5 clockwise from (217.7523, -148.4096) to (182.2477, -148.4096)
  arc A40 centre (200, -120) radius 29.5 clockwise from (215.6326, -145.0174) to (184.3674, -145.0174)
  circle C2 centre (177.1531, -95.4997) radius 4
  circle C3 centre (222.8469, -95.4997) radius 4
  circle C4 centre (177.1531, -144.5003) radius 4
  circle C5 centre (222.8469, -144.5003) radius 4
  dimension "d541" Text1-Height = 10
extrude "Extrude20" cut sketch "45mm PM Label" against normal blind 0.5
sketch "45mm DC Label" plane through (0, 0, 20) normal (0, 0, -1) x axis (1, 0, 0)
  line L1 (208, -98.7564) -> (208, -87.4692)
  line L2 (192, -87.4692) -> (192, -98.7564)
  line L3 (227.3973, -100.8162) -> (224.0432, -103.1648)
  line L4 (224.0432, -136.8352) -> (227.3973, -139.1838)
  line L5 (217.7523, -148.4096) -> (215.6326, -145.0174)
  line L6 (184.3674, -145.0174) -> (182.2477, -148.4096)
  line L7 (172.6027, -139.1838) -> (175.9568, -136.8352)
  line L8 (175.9568, -103.1648) -> (172.6027, -100.8162)
  line L9 (206, -64.9692) -> (208, -65.8761)
  line L10 (194, -64.9692) -> (206, -64.9692)
  line L11 (192, -65.8761) -> (194, -64.9692)
  curve K1
  curve K2
  curve K3
  curve K4
  line L12 (245, -121.2179) -> (245, -125.5)
  line L13 (248, -121.2179) -> (245, -121.2179)
  line L14 (248, -116.5) -> (248, -121.2179)
  line L15 (245, -116.5) -> (248, -116.5)
  line L16 (245, -114.5) -> (245, -116.5)
  line L17 (244.7744, -114.5) -> (245, -114.5)
  line L18 (155, -114.5) -> (155.2256, -114.5)
  line L19 (155, -116.5) -> (155, -114.5)
  line L20 (152, -116.5) -> (155, -116.5)
  line L21 (152, -121.2179) -> (152, -116.5)
  line L22 (155, -121.2179) -> (152, -121.2179)
  line L23 (155, -125.5) -> (155, -121.2179)
  line L24 (155.2256, -125.5) -> (155, -125.5)
  line L25 (245, -125.5) -> (244.7744, -125.5)
  arc A1 centre (200, -120) radius 22.7 clockwise from (208, -98.7564) to (192, -98.7564)
  arc A2 centre (200, -120) radius 33.5 clockwise from (192, -87.4692) to (208, -87.4692)
  closed curve K5 centre (200, -120)
  closed curve K6 centre (200, -120)
  arc A3 centre (200, -120) radius 27.5 clockwise from (226.4189, -112.3652) to (226.4189, -127.6348)
  closed curve K7 centre (200, -120)
  circle C1 centre (222.8469, -144.5003) radius 2.2
  circle C2 centre (222.8469, -95.4997) radius 2.2
  circle C3 centre (177.1531, -144.5003) radius 2.2
  circle C4 centre (177.1531, -95.4997) radius 2.2
  arc A4 centre (200, -120) radius 33.5 clockwise from (217.7523, -148.4096) to (182.2477, -148.4096)
  arc A5 centre (200, -120) radius 29.5 clockwise from (215.6326, -145.0174) to (184.3674, -145.0174)
  closed curve K8 centre (200, -120)
  closed curve K9 centre (200, -120)
  closed curve K10 centre (200, -120)
  closed curve K11 centre (200, -120)
  arc A6 centre (200, -120) radius 27.5 clockwise from (173.5811, -127.6348) to (173.5811, -112.3652)
  closed curve K12 centre (200, -120)
  closed curve K13 centre (200, -120)
  dimension "d544" Text1-Height = 10
extrude "Extrude21" cut sketch "45mm DC Label" against normal blind 0.5
sketch "Sketch18" plane through (0, -134.6, 0) normal (0, -1, 0) x axis (1, 0, 0)
  line L1 (-1.5, 9.5) -> (-1.5, 7)
  line L2 (1.5, 9.5) -> (-1.5, 9.5)
  line L3 (1.5, 7) -> (1.5, 9.5)
  line L4 (-1.5, 7) -> (1.5, 7)
  line L5 (-3.6, 6) -> (-3.6, 2)
  line L6 (3.6, 6) -> (-3.6, 6)
  line L7 (3.6, 2) -> (3.6, 6)
  line L8 (-3.6, 2) -> (3.6, 2)
  line L9 (18, 0) -> (-18, 0)
  line L10 (18, 10) -> (18, 0)
  line L11 (4, 10) -> (18, 10)
  line L12 (2, 12) -> (4, 10)
  line L13 (-2, 12) -> (2, 12)
  line L14 (-4, 10) -> (-2, 12)
  line L15 (-18, 10) -> (-4, 10)
  line L16 (-18, 0) -> (-18, 10)
  line L17 (5.8, 0) -> (18, 0)
  line L18 (5.8, 4) -> (5.8, 0)
  line L19 (18, 4) -> (5.8, 4)
  line L20 (18, 0) -> (18, 4)
  line L21 (9.8, 4) -> (5.8, 0)
  line L22 (11.4569, 0) -> (5.8, 0)
  line L23 (18, 2) -> (5.8, 2)
  line L24 (3.6, 2) -> (5.8, 2)
  line L25 (3.6, 4) -> (3.6, 2)
  line L26 (5.8, 4) -> (3.6, 4)
  line L27 (5.8, 2) -> (5.8, 4)
  point P11 (18, 0)
  point P18 (18, 0)
  point P22 (9.8, 4)
  point P24 (5.8, 2)
  point P25 (18, 2)
  point P27 (3.6, 4)
  point P19 (5.8, 0)
  point P21 (18, 4)
  horizontal L17
  vertical L18
  horizontal L19
  vertical L20
  coincident P11 P18
  horizontal L22
  coincident L19 P22
  midpoint L18 P24
  midpoint L20 P25
  horizontal L24
  vertical L25
  horizontal L26
  vertical L27
  midpoint L7 P27
  dimension "d634" distance P18 P19 = 12.2
  dimension "d635" distance P18 P21 = 4
  dimension "d636" angle L21 L22 = 45
extrude "Extrude34" cut sketch "Sketch18" profile of L9 L10 L17 L19 L20 L21 L23 against normal blind 9.2
extrude "Extrude35" cut sketch "Sketch18" profile of L7 L18 L19 L21 L23 L24 L25 L26 L27 against normal blind 4
sketch "Sketch19" plane through (-3.6, 0, 0) normal (1, 0, 0) x axis (0, 1, 0)
  line L1 (-126.9215, 2) -> (-134.6, 2)
  line L2 (-126.9215, 6) -> (-126.9215, 2)
  line L3 (-134.6, 6) -> (-126.9215, 6)
  line L4 (-134.6, 2) -> (-134.6, 6)
  line L5 (-130.6, 2) -> (-134.6, 2)
  line L6 (-130.6, 4) -> (-130.6, 2)
  line L7 (-134.6, 4) -> (-130.6, 4)
  line L8 (-134.6, 2) -> (-134.6, 4)
  line L9 (-133.1, 2) -> (-133.1, 4)
  line L10 (-132.1, 2) -> (-132.1, 4)
  line L11 (-132.1, 4) -> (-133.1, 3)
  line L12 (-132.1, 2) -> (-133.1, 3)
  point P2 (-134.6, 2)
  point P6 (-134.6, 2)
  point P14 (-133.1, 3)
  point P7 (-130.6, 2)
  point P9 (-134.6, 4)
  horizontal L5
  vertical L6
  horizontal L7
  parallel L6 L8
  coincident P2 P6
  midpoint L9 P14
  perpendicular L11 L12
  dimension "d641" distance P6 P7 = 4
  dimension "d642" distance P6 P9 = 2
  dimension "d643" = -1.5
  dimension "d644" = -2.5
extrude "Extrude36" cut sketch "Sketch19" profile of L1 L5 L6 L7 L11 L12 against normal blind 14.4
chamfer "Chamfer10" distance 1
sketch "Sketch20" plane through (130.0009, -75.0561, 0) normal (-0.866, 0.5, 0) x axis (-0.5, -0.866, 0)
  line L1 (120.3942, 1) -> (113.3942, 1)
  line L2 (120.3942, 35) -> (120.3942, 1)
  line L3 (113.3942, 35) -> (120.3942, 35)
  line L4 (113.3942, 1) -> (113.3942, 35)
  line L5 (109.3942, 35) -> (120.3942, 35)
  line L6 (109.3942, 27.6) -> (109.3942, 35)
  line L7 (120.3942, 27.6) -> (109.3942, 27.6)
  line L8 (120.3942, 35) -> (120.3942, 27.6)
  line L9 (113.3942, 23.6) -> (109.3942, 27.6)
  line L10 (115.051, 27.6) -> (109.3942, 27.6)
  line L11 (120.3942, 35) -> (109.3942, 35)
  line L12 (120.3942, 36) -> (120.3942, 35)
  line L13 (109.3942, 36) -> (120.3942, 36)
  line L14 (109.3942, 35) -> (109.3942, 36)
  line L15 (113.3942, 36) -> (113.3942, 35)
  point P4 (120.3942, 35)
  point P6 (120.3942, 35)
  point P10 (113.3942, 23.6)
  point P5 (113.3942, 35)
  point P15 (113.3942, 35)
  point P16 (113.3942, 36)
  point P7 (109.3942, 35)
  point P9 (120.3942, 27.6)
  point P12 (120.3942, 35)
  point P14 (109.3942, 36)
  horizontal L5
  vertical L6
  horizontal L7
  vertical L8
  coincident P4 P6
  horizontal L10
  coincident L4 P10
  horizontal L11
  vertical L12
  horizontal L13
  vertical L14
  coincident P5 P15
  coincident L13 P16
  perpendicular L13 L15
  dimension "d648" distance P6 P7 = 11
  dimension "d649" distance P6 P9 = 7.4
  dimension "d650" angle L9 L10 = 45
  dimension "d651" distance P7 P12 = 11
  dimension "d652" distance P7 P14 = 1
extrude "Extrude37" add sketch "Sketch20" profile of L4 L5 L6 L7 L9 L11 L13 L14 L15 against normal blind 9.2
extrude "Extrude38" cut of existing geometry blind -4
